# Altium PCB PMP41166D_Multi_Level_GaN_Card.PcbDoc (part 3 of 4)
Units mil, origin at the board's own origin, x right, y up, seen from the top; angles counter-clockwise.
Board outline 3221.72 x 1840 mil, 6 copper layers (Top Layer, Signal Layer 1, Signal Layer 2, Signal Layer 3, Signal Layer 4, Bottom Layer), stack 51.8 mil thick; 155 components, 123 nets, 580 pads, 278 vias.
Unrouted connection lines stored in the file: 2.
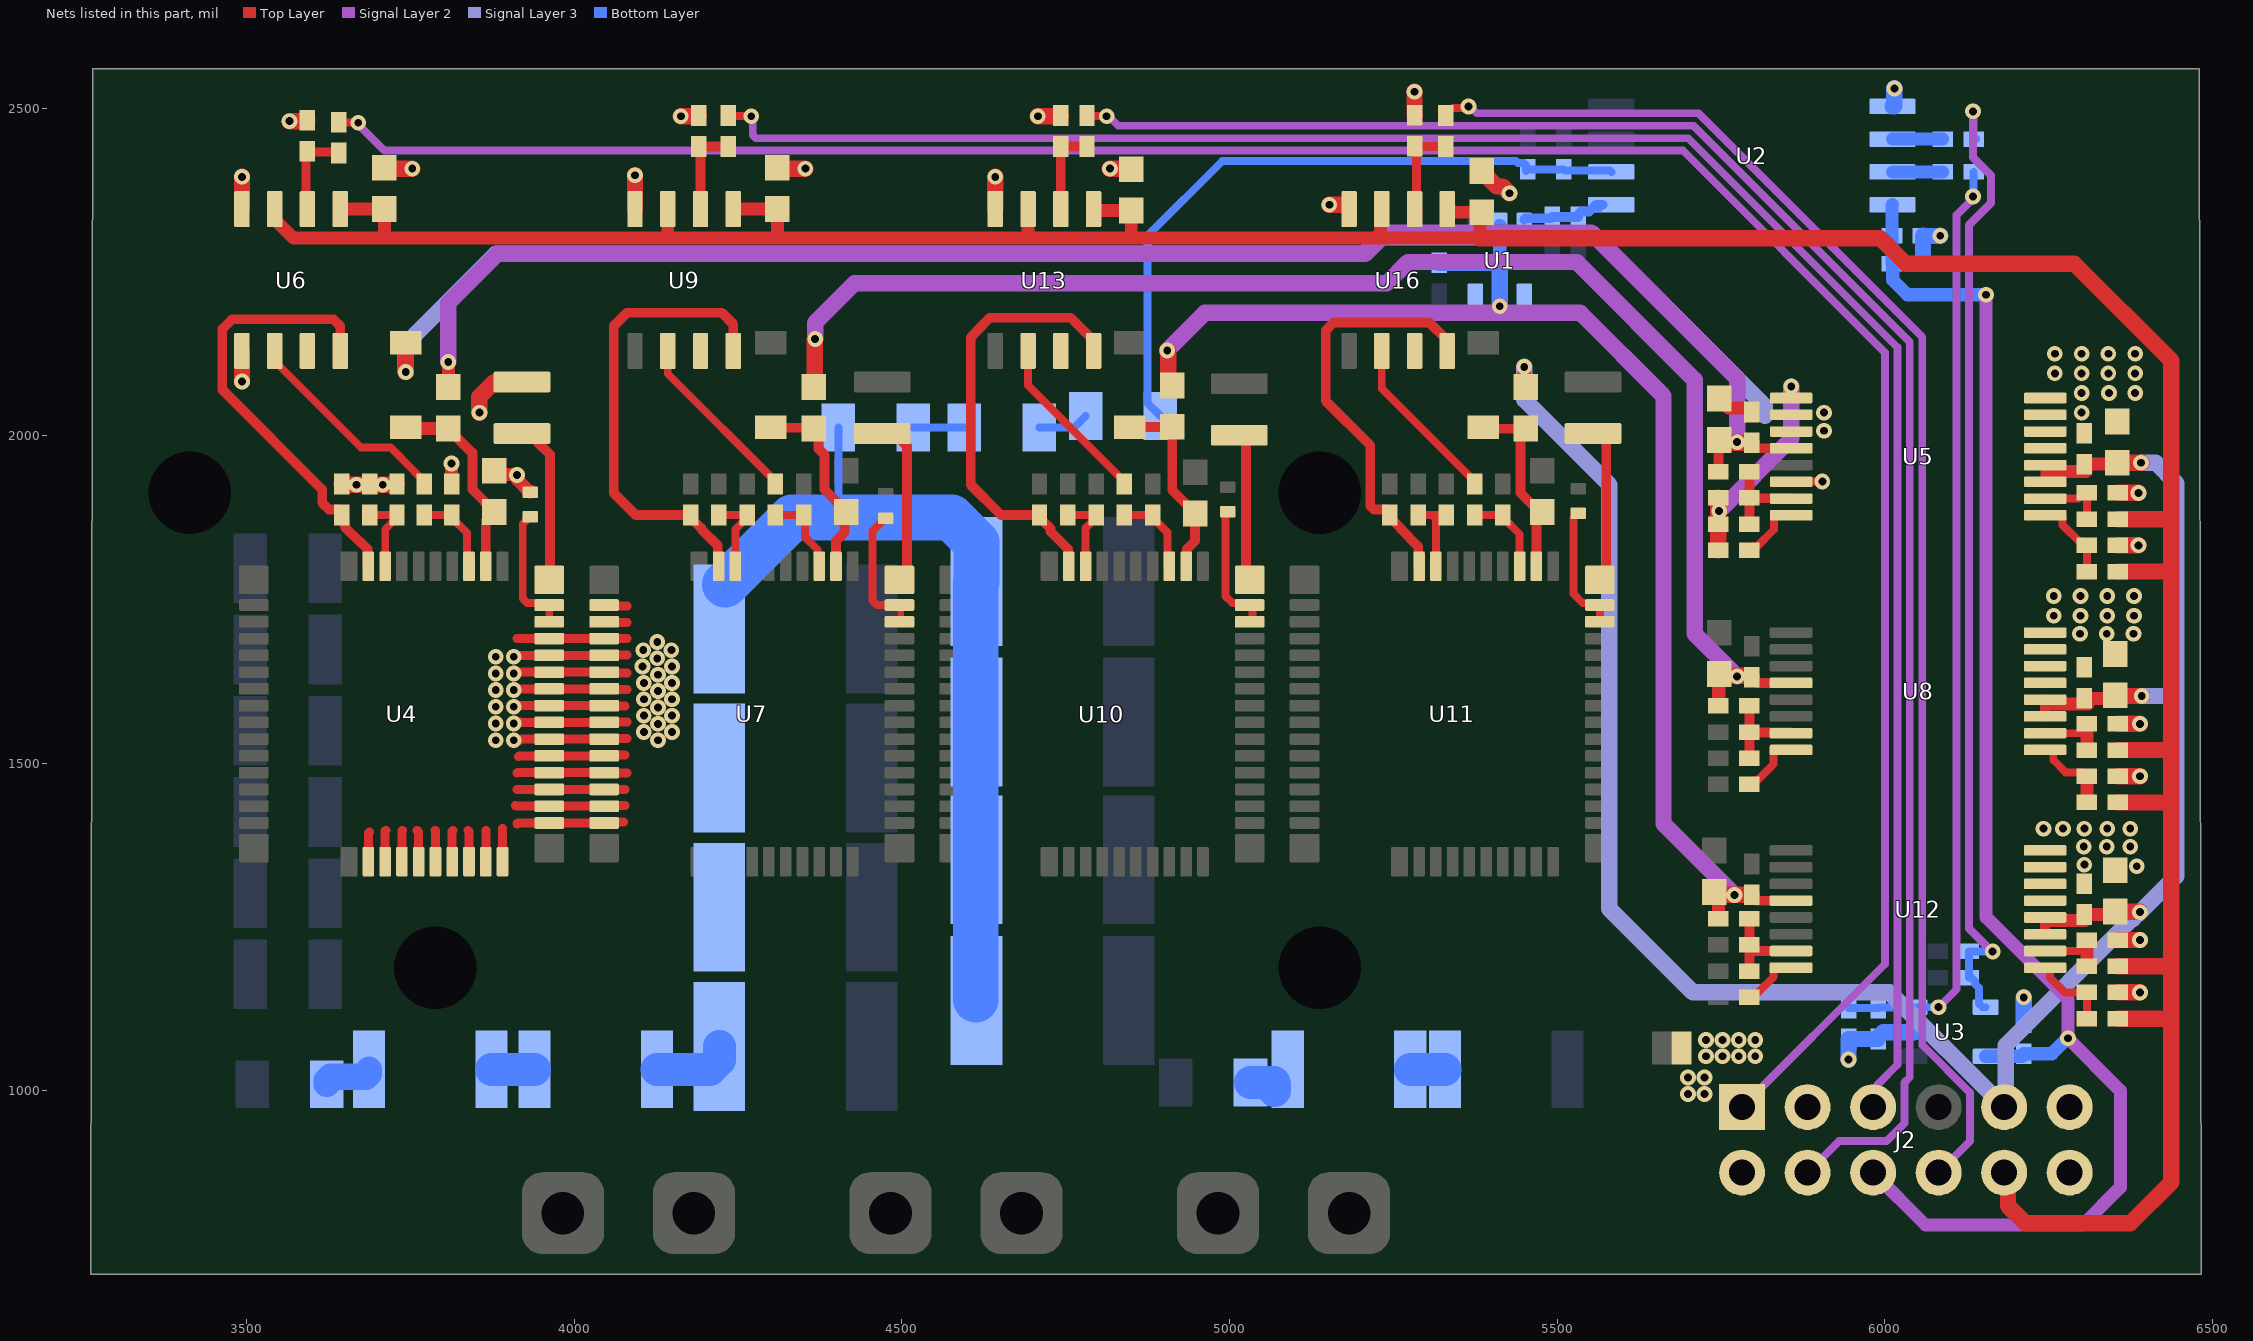
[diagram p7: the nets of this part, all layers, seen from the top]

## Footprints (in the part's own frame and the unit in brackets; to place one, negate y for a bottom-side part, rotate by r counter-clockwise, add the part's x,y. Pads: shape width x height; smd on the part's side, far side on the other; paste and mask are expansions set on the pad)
0402 [mm] "0402 from SM-752 data"
  rect 0.8x0.6 smd: 1(-0.6,0) 2(0.6,0)
  silkscreen extent -1.22,-0.52 1.22,0.52, body extent -0.55,-0.3 0.55,0.3, height 0.6
0603 [mm] "0603 from SM-752 data"
  rect 1x0.95 smd: 1(-0.8,0) 2(0.8,0)
  silkscreen extent -1.52,-0.69 1.52,0.69, body extent -0.87,-0.47 0.87,0.47, height 1
1206 [mm] "1206 from SM-752 data"
  rect 1.3x1.85 smd: 1(-1.45,0) 2(1.45,0)
  body extent -1.7,-0.9 1.7,0.9, height 1.35
1210 [mm] "1210 from SM-752 data"
  rect 1.3x2.7 smd: 1(-1.45,0) 2(1.45,0)
  silkscreen extent -2.32,-1.57 2.32,1.57, body extent -1.7,-1.35 1.7,1.35, height 1.35
AB12-DEST [mil] "Samtec right angle header, pins flipped from convention"
  rect 70x70 hole 40: 1(-250,50)
  round 70 hole 40: 2(-250,-50) 3(-150,50) 4(-150,-50) 5(-50,50) 6(-50,-50) 7(50,50) 8(50,-50) 9(150,50) 10(150,-50) 11(250,50) 12(250,-50)
  silkscreen extent -300,-479 300,100, body extent -300,-440 300,63, height 219
CKG57N [mm] "Chip Capacitor, Body 6.0x5.0x5.0mm,"
  rect 2x5 smd: 1(-2.95,0) 2(2.95,0)
  silkscreen extent -3.2,-2.8 3.2,2.8, body extent -3.3,-2.75 3.3,2.75, height 5.5
D0008B-MFG [mm]
  rrect17% 1.4x0.6 smd paste+0 mask+0: 1(-2.75,1.905) 2(-2.75,0.635) 3(-2.75,-0.635) 4(-2.75,-1.905) 5(2.75,-1.905) 6(2.75,-0.635) 7(2.75,0.635) 8(2.75,1.905)
  silkscreen extent -4.14,-2.5 1.5,2.5, body extent -3,-2.45 3,2.45, height 1.75
DBV0005A_N [mm] "SOT23, 5-Leads, Body 2.9x1.6mm, Pitch 0.95mm, Lead Span 2.8mm, IPC Medium Density"
  rrect17% 1x0.6 smd: 1(-1.375,0.95) 2(-1.375,0) 3(-1.375,-0.95) 4(1.375,-0.95) 5(1.375,0.95)
  silkscreen extent -0.25,-1.55 0.25,1.55, body extent -1.42,-1.46 1.42,1.46, height 1.09
DHA0016A-MFG [mm] "Recommended Land Pattern"
  rrect24% 1.65x0.41 smd paste+0 mask+0: 1(-4.925,2.275) 2(-4.925,1.625) 3(-4.925,0.975) 4(-4.925,0.325) 5(-4.925,-0.325) 6(-4.925,-0.975) 7(-4.925,-1.625) 8(-4.925,-2.275) 9(4.925,-2.275) 10(4.925,-1.625) 11(4.925,-0.975) 12(4.925,-0.325) 13(4.925,0.325) 14(4.925,0.975) 15(4.925,1.625) 16(4.925,2.275)
  silkscreen extent -6.43,-2.98 3.5,2.98, body extent -5.15,-2.93 5.15,2.93, height 2.6
DO-213AB [mm] "VISHAY"
  rect 1.25x3 smd: 1(-2.375,0) 2(2.375,0)
  silkscreen extent -2.79,-2.92 1.4,1.4, body extent -2.6,-1.34 2.6,1.33, height 2.66
DWV0008A-MFG [mm] "Recommended Land Pattern"
  rrect17% 1.8x0.6 smd paste+0 mask+0: 1(-5.45,1.905) 2(-5.45,0.635) 3(-5.45,-0.635) 4(-5.45,-1.905) 5(5.45,-1.905) 6(5.45,-0.635) 7(5.45,0.635) 8(5.45,1.905)
  silkscreen extent -7.1,-2.98 3.8,2.98, body extent -5.75,-2.93 5.75,2.93, height 2.8
FCC_disclaimer [mil]
"FP-GRM155R61E225KE11D_0402 (1005 metric)-MFG" [mm]
  rrect22% 0.45x0.6 smd paste+0 mask+0: 1(-0.475,0) 2(0.475,0)
  silkscreen extent -0.6,-0.64 0.6,0.65, body extent -0.5,-0.25 0.5,0.25, height 0.7
FP-MPIA2510V2-4R7-R_1008-MFG [mm]
  rrect13% 0.8x2.2 smd paste+0 mask+0: 1(-1,0) 2(1,0)
  silkscreen extent -0.23,-1.1 0.23,1.1, body extent -1.25,-1 1.25,1, height 1.05
IEC_HighVoltage_Small [mil]
  silkscreen extent -107,-88 107,97
IEC_HotSurface_Small [mil]
  silkscreen extent -107,-93 107,92
Mill-Max_3621-0-32-xx-00-00-08-0 [mm] "PCB Pin, 0.04\" DIA, R/A, Edge-Mount"
  rrect50% 3.18x3.18 hole 1.65: 1(0,2.388)
  body extent -1.59,-5.06 1.59,3.98, height 1.57
Net-Tie_50milWide_30milLong [mil] "50mil net tie, no solder mask opening, no solder paste"
  rect 30x50 smd paste-20 mask-20: 1(-15,0) 2(15,0)
RQS0052C-C01-MFG [mm]
  rrect9% 1.15x1.1 smd paste+0 mask+0: 1(-5.725,5.2) 16(-5.725,-5.2) 27(5.725,-5.2) 42(5.725,5.2)
  rrect22% 1.15x0.45 smd paste+0 mask+0: 2(-5.725,4.225) 3(-5.725,3.575) 4(-5.725,2.925) 5(-5.725,2.275) 6(-5.725,1.625) 7(-5.725,0.975) 8(-5.725,0.325) 9(-5.725,-0.325) 10(-5.725,-0.975) 11(-5.725,-1.625) 12(-5.725,-2.275) 13(-5.725,-2.925) 14(-5.725,-3.575) 15(-5.725,-4.225) 28(5.725,-4.225) 29(5.725,-3.575) 30(5.725,-2.925) 31(5.725,-2.275) 32(5.725,-1.625) 33(5.725,-0.975) 34(5.725,-0.325) 35(5.725,0.325) 36(5.725,0.975) 37(5.725,1.625) 38(5.725,2.275) 39(5.725,2.925) 40(5.725,3.575) 41(5.725,4.225)
  rrect15% 0.665x1.15 smd paste+0 mask+0: 17(-2.043,-5.725) 52(-2.043,5.725)
  rrect22% 0.45x1.15 smd paste+0 mask+0: 18(-1.285,-5.725) 19(-0.635,-5.725) 20(0.015,-5.725) 21(0.665,-5.725) 22(1.315,-5.725) 23(1.965,-5.725) 24(2.615,-5.725) 25(3.265,-5.725) 26(3.915,-5.725) 43(3.915,5.725) 44(3.265,5.725) 45(2.615,5.725) 46(1.965,5.725) 47(1.315,5.725) 48(0.665,5.725) 49(0.015,5.725) 50(-0.635,5.725) 51(-1.285,5.725)
  silkscreen extent -7.02,-6.05 4.77,6.05, body extent -6,-6 6,6, height 1
SOD-123 [mm] "On Semi recommended land pattern"
  rect 0.915x1.22 smd: 1(-1.637,0) 2(1.637,0)
  silkscreen extent -2.74,-1.17 2.03,1.17, body extent -1.93,-0.9 1.93,0.9, height 1.35
TP_H045P075 [mm] "TP_H0.45P0.75"
  round 0.75 hole 3.2: 1(0,0)
WEEE_Minimum [mil] "WEEElie bin"
  silkscreen extent -95,-172 99,104

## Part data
BULK PGND SW TP1 TP2 TP3: library part CMP-0082316-1, Manufacturer=Mill-Max, Supplier Part Number 1=575-3621032150000
C1 C25 C69: library part CMP-0081457-1, "CAP, CERM, 1 µF, 10 V,+/- 20%, X5R, 0402", Cap_Case=0402, Manufacturer="Yageo America", TempCo=X5R, Tolerance_%=20%, Value2=10V, ValueDisplayed=1µF
C2 C4 C23 C28 C51 C52 C65 C67 C70 C72 C74: library part CMP-0080610-1, "CAP, CERM, 0.1 µF, 25 V,+/- 10%, X7R, AEC-Q200 Grade 1, 0402", Cap_Case=0402, Manufacturer=TDK, Supplier Part Number 1=445-6902-1-ND, TempCo=X7R, Tolerance_%=10%, Value2=25V, ValueDisplayed=0.1µF
C3 C22 C64 C66 C71 C73: library part CMP-0007007-5, "CAP, CERM, 10 uF, 25 V, +/- 20%, X5R, 0603", Cap_Case=0603, Manufacturer=TDK, Supplier Part Number 1=445-9015-1-ND, TempCo=X5R, Tolerance_%=20%, Value1="0.004639 ohm", Value2=25V, ValueDisplayed=10uF
C5 C6 C7 C8 C9 C10: library part CMP-0009136-2, "CAP, CERM, 0.1 uF, 630 V, +/- 10%, X7T, 1210", Cap_Case=1210, Manufacturer=TDK, Supplier Part Number 1=445-7766-1-ND, TempCo=X7T, Tolerance_%=10%, Value1=Unknown, Value2=630V, ValueDisplayed=0.1uF
C11 C30 C44 C58: library part CMP-0007344-5, "CAP, CERM, 10 uF, 25 V, +/- 20%, X5R, 0603", Cap_Case=0603, Manufacturer=MuRata, Supplier Part Number 1=490-7202-1-ND, TempCo=X5R, Tolerance_%=20%, Value1=Unknown, Value2=25V, ValueDisplayed=10uF
C12 C13 C14 C15 C16 C17 C18 C19: library part CMP-0009428-1, "CAP, CERM, 2.2 uF, 450 V, +/- 20%, X7T, AEC-Q200 Grade 1, 6x5x5mm", Cap_Case=2220, Manufacturer=TDK, Supplier Part Number 1=445-7109-1-ND, TempCo=X7T, Tolerance_%=20%, Value1=Unknown, Value2=450V, ValueDisplayed=2.2uF
C20 C57 C80 C96: library part CMP-0007359-4, "CAP, CERM, 0.1 uF, 6.3 V, +/- 10%, X7R, 0603", Cap_Case=0603, Manufacturer=MuRata, Supplier Part Number 1=GRM188R70J104KA01D-ND, TempCo=X7R, Tolerance_%=10%, Value1=Unknown, Value2=6.3V, ValueDisplayed=0.1uF
C21 C40 C45 C59: library part CMP-0078265-1, "CAP, CERM, 0.22 µF, 16 V,+/- 10%, X7R, AEC-Q200 Grade 1, 0402", Cap_Case=0402, Manufacturer=MuRata, Supplier Part Number 1=490-10671-1-ND, TempCo=X7R, Tolerance_%=10%, Value2=16V, ValueDisplayed=0.22µF
C24 C68 C75: library part CMP-0006691-2, "CAP, CERM, 470 pF, 50 V, +/- 10%, X7R, 0402", Cap_Case=0402, Manufacturer=MuRata, Supplier Part Number 1=490-1300-1-ND, TempCo=X7R, Tolerance_%=10%, Value1=Unknown, Value2=50V, ValueDisplayed=470pF
C26 C63 C86 C98: library part CMP-0006251-2, "CAP, CERM, 68 pF, 50 V, +/- 5%, C0G/NP0, 0402", Alternate Manufacturer=Murata, Alternate PartNumber=GRM1555C1H680JA01D, Cap_Case=0402, Manufacturer=TDK, Supplier Part Number 1=445-1245-1-ND, TempCo=C0G/NP0, Tolerance_%=5%, Value1=Unknown, Value2=50V, ValueDisplayed=68pF
C27 C42 C47 C61: library part CMP-0006308-1, "CAP, CERM, 100 pF, 50 V, +/- 5%, C0G/NP0, AEC-Q200 Grade 1, 0402", Cap_Case=0402, Manufacturer=TDK, Supplier Part Number 1=445-5596-1-ND, TempCo=C0G/NP0, Tolerance_%=5%, Value1=Unknown, Value2=50V, ValueDisplayed=100pF
C29 C43 C48 C62: library part CMP-0089929-1, "2.2µF ±10% 25V Ceramic Capacitor X5R 0402 (1005 Metric)", Digikey Part Number=490-12703-1-ND, Manufacturer=Murata, Mouser Part Number=81-GRM155R61E225KE1D, Operating Temperature Range="-55°C to +85°C", TempCo=15%, Temperature Characteristic=X5R, Tolerance_%=10%, ValueDisplayed=2.2uF, Voltage=25V
C31 C41 C46 C60: library part CMP-0006439-2, "CAP, CERM, 22 pF, 50 V, +/- 5%, C0G/NP0, 0402", Cap_Case=0402, Manufacturer=MuRata, Supplier Part Number 1=81-GRM1555C1H220JA1D, TempCo=C0G/NP0, Tolerance_%=5%, Value1=Unknown, Value2=50V, ValueDisplayed=22pF
C49: library part CMP-0006297-2, "CAP, CERM, 0.1 uF, 50 V, +/- 10%, X7R, 0402", Cap_Case=0402, Manufacturer=TDK, Supplier Part Number 1=445-5932-1-ND, TempCo=X7R, Tolerance_%=10%, Value1="0.039064 ohm", Value2=50V, ValueDisplayed=0.1uF
C50 C100: library part CMP-0006455-2, "CAP, CERM, 330 pF, 50 V, +/- 1%, C0G/NP0, 0402", Cap_Case=0402, Manufacturer=MuRata, Supplier Part Number 1=490-6234-1-ND, TempCo=C0G/NP0, Tolerance_%=1%, Value1=Unknown, Value2=50V, ValueDisplayed=330pF
C53 C54 C55: library part CMP-0078625-1, "CAP, CERM, 1 µF, 25 V,+/- 20%, X5R, 0402", Cap_Case=0402, Manufacturer=MuRata, Supplier Part Number 1=490-10018-1-ND, TempCo=X5R, Tolerance_%=20%, Value2=25V, ValueDisplayed=1µF
C56: library part CMP-0006663-2, "CAP, CERM, 2200 pF, 25 V, +/- 10%, X7R, 0402", Cap_Case=0402, Manufacturer=MuRata, Supplier Part Number 1=490-5419-1-ND, TempCo=X7R, Tolerance_%=10%, Value1=Unknown, Value2=25V, ValueDisplayed=2200pF
D2 D3 D5 D6: library part CMP-0082173-3, "Diode, Zener, 150V", Manufacturer=Vishay-Semiconductor, PartNumber=ZGL41-150A-E3/96, Power_W=1W
D8 D9 D10 D11: library part CMP-0005769-2, "Diode, Zener, 16 V, 500 mW, AEC-Q101, SOD-123", Manufacturer="Diodes Inc.", Power_W=500mW, Supplier Part Number 1=BZT52C16-FDICT-ND, Value1=0.5W
J2: library part CMP-0075414-2, "Header, 100mil, 6x2, Gold, R/A, TH", Color=Black, Current_A=6.3A, Manufacturer=Samtec, Supplier Part Number 1=SAM1037-06-ND, Voltage_V=550V
L4 L5 L6 L7: library part CMP-0090507-1, "4.7µH Shielded Molded Inductor 1.22A 262mOhm Max 1008 (2520 Metric)", Digikey Part Number=283-4799-1-ND, Manufacturer=Eaton, Mouser Part Number=704-MPIA2510V2-4R7-R, Operating Temperature Range="-40°C to +125°C", Self Resonant Frequency=25MHz, Test Frequency=1MHz, Tolerance_%=20%
Logo1: library part CMP-0074769-1
Logo3: library part CMP-0074847-1, "FCC_disclaimer"
LOGO5: library part CMP-0074837-1, "IEC 61010-1 Hot Surface Warning"
LOGO6: library part CMP-0074835-1, "IEC 61010-1 High Voltage Warning"
NT1: library part CMP-0078142-4, "Single point connection between nets.", Manufacturer=N/A
R1 R2 R3 R4: library part CMP-0026918-5, "RES, 3.3 k, 5%, 0.063 W, AEC-Q200 Grade 0, 0402", Manufacturer=Vishay-Dale, Power_W=63mW, Supplier Part Number 1=541-3.3KJCT-ND, TempCo="200 ppm/C", Tolerance_%=5%, Value2=0.063W, Value_Code=3k30, ValueDisplayed=3.3k
R5 R8 R11 R25: library part CMP-0025883-3, "RES, 0, 5%, 0.1 W, 0603", Manufacturer=Rohm, Power_W=100mW, Supplier Part Number 1=RHM0.0GCT-ND, TempCo="400 ppm/C", Tolerance_%=5%, Value2=0.1W, Value_Code=0000, ValueDisplayed=0
R6 R9 R12 R27: library part CMP-0026902-3, "RES, 300, 5%, 0.063 W, AEC-Q200 Grade 0, 0402", Manufacturer=Vishay-Dale, Power_W=63mW, Supplier Part Number 1=541-300JCT-ND, TempCo="200 ppm/C", Tolerance_%=5%, Value2=0.063W, Value_Code=300R, ValueDisplayed=300
R7 R10 R13 R14: library part CMP-0026720-1, "RES, 69.8 k, 1%, 0.063 W, 0402", Manufacturer=Rohm, Power_W=63mW, TempCo="100 ppm/C", Tolerance_%=1%, Value2=0.063W, Value_Code=69k8, ValueDisplayed=69.8k
R15 R19 R20 R24 R26 R33: library part CMP-0065360-1, "RES, 10.0 k, .1%, .0625 W, 0402", Manufacturer="Yageo America", Power_W=62.5mW, Supplier Part Number 1=YAG1346CT-ND, TempCo="25 ppm/C", Tolerance_%=0.1%, Value1=.1%, Value2=.0625W, Value_Code=10k0, ValueDisplayed=10.0k
R16 R21 R29: library part CMP-0026463-2, "RES, 5.11 k, 1%, 0.063 W, AEC-Q200 Grade 0, 0402", Manufacturer=Vishay-Dale, Power_W=63mW, Supplier Part Number 1=541-5.11KLCT-ND, TempCo="100 ppm/C", Tolerance_%=1%, Value2=0.063W, Value_Code=5k11, ValueDisplayed=5.11k
R17 R22 R31: library part CMP-0026723-1, "RES, 180 k, 1%, 0.063 W, 0402", Manufacturer="Yageo America", Power_W=63mW, Supplier Part Number 1=311-180KLRCT-ND, TempCo="100 ppm/C", Tolerance_%=1%, Value2=0.063W, Value_Code=180k
R18 R23 R32: library part CMP-0026323-1, "RES, 38.3 k, 1%, 0.063 W, 0402", Manufacturer=Vishay-Dale, Power_W=63mW, Supplier Part Number 1=541-38.3KLCT-ND, TempCo="100 ppm/C", Tolerance_%=1%, Value2=0.063W, Value_Code=38k3, ValueDisplayed=38.3k
R28 R40 R60 R74: library part CMP-0026404-2, "RES, 49.9, 1%, 0.063 W, AEC-Q200 Grade 0, 0402", Manufacturer=Vishay-Dale, Power_W=63mW, Supplier Part Number 1=541-49.9LCT-ND, TempCo="100 ppm/C", Tolerance_%=1%, Value2=0.063W, Value_Code=49R9, ValueDisplayed=49.9
R30 R63: library part CMP-0018790-2, "RES, 10.0, 0.1%, 1 W, 1206", Manufacturer=Vishay-Dale, Power_W=1W, Supplier Part Number 1=PHP10.0ACT-ND, TempCo="25 ppm/C", Tolerance_%=0.1%, Value_Code=10R0, ValueDisplayed=10.0
R42 R46 R48: library part CMP-0018215-2, "RES, 348 k, 1%, 0.25 W, 1206", Manufacturer="Yageo America", Power_W=250mW, Supplier Part Number 1=311-348KFRCT-ND, TempCo="100 ppm/C", Tolerance_%=1%, Value2=0.25W, Value_Code=348k
R53: library part CMP-0026555-2, "RES, 7.50 k, 1%, 0.063 W, AEC-Q200 Grade 0, 0402", Manufacturer=Vishay-Dale, Power_W=63mW, Supplier Part Number 1=541-7.50KLCT-ND, TempCo="100 ppm/C", Tolerance_%=1%, Value2=0.063W, Value_Code=7k50, ValueDisplayed=7.50k
TH1 TH2 TH3 TH4: library part CMP-0003719-1, "Testpoint", Manufacturer="Texas Instruments", PartNumber=TP_H0.45P0.75
U1: library part CMP-0035558-1, "Single Output LDO, 150 mA, Fixed 5 V Output, 2.5 to 24 V Input, with Ultra-Low IQ, 5-pin SOT-23 (DBV), -40 to 125 degC, Green (RoHS & no Sb/Br)", Manufacturer="Texas Instruments"
U2: library part CMP-0124041-1, "Precision, 2V Input, Basic and Reinforced Isolated Amplifiers With Fixed-Gain Differential Output", Input Bias Current=3.5nA, Input Offset Voltage=0.2mV, Manufacturer="Texas Instruments", Max Supply Voltage=5.5V, Min Supply Voltage=3V, Operating Temperature Range="-40°C to +125°C", Output Current Per Channel=11mA, Voltage Gain=1V/V
U3: library part CMP-0750075-1, "10-MHz, RRIO, CMOS Operational Amplifier for Cost-Sensitive Systems, DBV0005A (SOT-23-5)", Alternate Manufacturer="Texas Instruments"
U4 U7 U10 U11: library part CMP-0094892-1, "650-V 30-mΩ GaN FET with Integrated Driver, Protection, and Temperature Reporting", Manufacturer="Texas Instruments", Max Supply Voltage=18V, Min Supply Voltage=7.5V, Nominal Supply Current=16mA, Operating Temperature Range="-40°C to +150°C", Output Voltage=520V, Part Number=LMG3525R030-Q1
U5 U8 U12: library part CMP-0126653-2, "Automotive 2.0W, 12V VIN, High-Density, > 5kVRMS, Isolated DC/DC Module", Manufacturer="Texas Instruments", Max Supply Voltage=20V, Min Supply Voltage=5.5V, Operating Temperature Range="-40°C to +150°C", Output Voltage=-2-8/12-18V
U6 U9 U13 U16: library part CMP-0089765-2, "General Purpose Digital Isolator 3000Vrms 1 Channel 100Mbps 85kV/µs CMTI 8-SOIC (0.154\", 3.90mm Width)", Digikey Part Number=296-51194-1-ND, Manufacturer="Texas Instruments", Max Supply Voltage=5.5V, Min Supply Voltage=2.25V, Mouser Part Number=595-ISO7710FDR, Nominal Supply Current=156-311mA, Operating Temperature Range="-55°C to +125°C"

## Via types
v1: diameter 24, hole 12, Top Layer to Bottom Layer, tented both sides, 278 vias

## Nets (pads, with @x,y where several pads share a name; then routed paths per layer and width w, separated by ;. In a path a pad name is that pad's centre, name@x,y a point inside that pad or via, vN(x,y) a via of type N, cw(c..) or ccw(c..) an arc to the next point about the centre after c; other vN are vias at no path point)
3V3: C52.2 C53.2 C55.2 J2.6 U2.8 U3.5 | length 2287.8
  Signal Layer 2 w20: J2.6@5982.5,875 6062.5,795 6302.5,795 6360,852.5 6360,1000 v1(6280,1080) 6280,1139.5 6155,1264.5 v1(6155,2215)
  Bottom Layer w20: U2.8@6012.07,2352.5 6011.38,2351.81 C52.2@6011.38,2305 C55.2@6011.38,2262.5 6012.5,2261.38 6012.5,2237.5 6035,2215 v1(6155,2215) ; U3.5@6154.13,1052.6 6210.69,1052.6 6212.5,1054.41 C53.2@6212.5,1056.38 6255.3,1056.38 6278.92,1080 v1(6280,1080)
5Vp: C20.1 C57.1 C80.1 C96.1 J2.10 R15.2 R16.2 R20.2 R21.2 R26.2 R29.2 U6.1 U6.3 U9.1 U9.3 U13.1 U13.3 U16.1 U16.3 | length 5636.9
  Top Layer w13.78: U6.3@3542.5,2330.02 U6.3@3542.5,2345.77 ; U9.3@4142.5,2335 U9.3@4142.5,2345.77 ; U13.3@4692.5,2323.57 U13.3@4692.5,2345.77
  Top Layer w19.68: U6.3@3542.5,2330.02 3571.15,2301.37 3710,2301.37 ; U6.1@3642.5,2345.77 3642.62,2345.89 3709.88,2345.89 C20.1@3710,2346 3710,2301.37 ; U9.3@4142.5,2335 4142.5,2301.37 ; U9.1@4242.5,2345.77 4242.62,2345.89 4309.88,2345.89 C57.1@4310,2346 4310,2303.87 4307.5,2301.37 ; U13.3@4692.5,2323.57 4692.5,2301.37 ; U13.1@4792.5,2345.77 4792.5,2345.47 4794.47,2343.5 C80.1@4850,2343.5 4850,2303.87 4847.5,2301.37 ; U16.3@5232.5,2345.77 5230.53,2343.8 5230.53,2301.9 5230,2301.37 ; U16.1@5337.5,2345.77 5342.26,2341 C96.1@5385,2341 5382.5,2338.5 5382.5,2301.37 5230,2301.37 ; 3710,2301.37 4142.5,2301.37 ; 4142.5,2301.37 4307.5,2301.37 ; 4307.5,2301.37 4692.5,2301.37 ; 4692.5,2301.37 4847.5,2301.37 ; 4847.5,2301.37 5230,2301.37
  Top Layer w25: 5382.5,2301.37 5993.63,2301.37 6032.5,2262.5 6289.55,2262.5 6437.5,2114.55 6437.5,1875 ; J2.10@6182.5,875 6188.42,869.08 6188.42,824.08 6215,797.5 6375,797.5 6437.5,860 6437.5,1112.5 ; R29.2@6356.12,1110 6435,1110 6437.5,1112.5 ; R26.2@6356.12,1190 6437.5,1190 ; R21.2@6356.12,1440 6435,1440 6437.5,1442.5 ; R20.2@6356.12,1520 6437.5,1520 ; R16.2@6356.12,1792.5 6437.5,1792.5 ; R15.2@6356.12,1872.5 6435,1872.5 6437.5,1875 ; 6437.5,1112.5 6437.5,1190 ; 6437.5,1190 6437.5,1442.5 ; 6437.5,1442.5 6437.5,1520 ; 6437.5,1520 6437.5,1792.5 ; 6437.5,1792.5 6437.5,1875
12Vp: C3.1 C4.1 C64.1 C65.1 C71.1 C72.1 J2.9 R11.1 U5.3 U5.4 U8.3 U8.4 U12.3 U12.4 | length 3343.2
  Top Layer w12: U12.4@6245,1264.41 U12.4@6245.59,1265 ; U8.4@6245,1596.91 U8.4@6245.98,1597.89 ; U5.4@6245.3,1955 U5.4@6245.98,1955.69 ; C72.1@6301.12,1265 C72.1@6305,1268.88 ; C65.1@6304.02,1597.89 C65.1@6305,1598.88 ; C4.1@6304.31,1955.69 C4.1@6305,1956.38 ; C71.1@6347.87,1268.88 C71.1@6352.5,1273.5 ; C64.1@6347.87,1598.88 C64.1@6352.5,1603.5 ; C3.1@6352.87,1956.38 C3.1@6355,1958.5
  Top Layer w15: U12.3@6245,1238.82 U12.4@6245,1264.41 ; U8.3@6245,1571.32 U8.4@6245,1596.91 ; U5.3@6245.3,1929.41 U5.4@6245.3,1955 ; C71.1@6352.5,1273.5 C71.1@6353,1273 ; v1@6389.5,1273 v1(6390,1272.5)
  Top Layer w20: R11.1@5450,2074 v1(5450,2105) ; U12.4@6250,1260 C72.1@6305.53,1260 ; 6251.67,1945 C4.1@6307.5,1945 ; U8.4@6252.5,1590 C65.1@6310.53,1590 ; C72.1@6305,1268.88 C71.1@6347.87,1268.88 ; C65.1@6305,1598.88 C64.1@6347.87,1598.88 ; C4.1@6305,1956.38 C3.1@6352.87,1956.38
  Top Layer w25: C64.1@6352.5,1603.5 6353.5,1602.5 v1(6392.5,1602.5) ; C71.1@6353,1273 v1@6389.5,1273 ; C3.1@6355,1958.5 v1(6391.62,1958.5)
  Signal Layer 3 w25: v1(5450,2105) 5450,2055 5580,1925 5580,1277.5 5707.5,1150 6007.5,1150 J2.9@6182.5,975 6185,977.5 6185,1069.55 6376.95,1261.5 6379,1261.5 v1(6390,1272.5) 6445,1327.5 6445,1602.5 ; v1(6391.62,1958.5) 6414,1958.5 6445,1927.5 6445,1602.5 ; v1(6392.5,1602.5) 6445,1602.5
CFLYSENSE: C56.1 R48.1 R53.2 U2.2 | length 1048.9
  Bottom Layer w12: R48.1@4894.59,2030 4875,2049.59 4875,2305 4989,2419 5437.38,2419 5440.25,2416.13 5449.19,2416.13 5452.5,2412.82 R53.2@5452.5,2403.88 ; R53.2@5455,2406.38 C56.1@5510,2406.38 5511.94,2404.44 5580.99,2404.44 U2.2@5582.93,2402.5
HFFET_H2A: J2.1 R28.1 | length 3749.9
  Top Layer w12: R28.1@3640,2478.62 3640.56,2478.06 3669.44,2478.06 v1(3670,2477.5)
  Signal Layer 2 w12: v1(3670,2477.5) 3670,2475 3710,2435 5692.5,2435 6000.5,2127 6000.5,1193 J2.1@5782.5,975
HFFET_H3A: J2.5 R40.1 | length 3121.7
  Top Layer w12: R40.1@4235,2488.62 4235.56,2488.06 4269.44,2488.06 v1(4270,2487.5)
  Signal Layer 2 w12: v1(4270,2487.5) 4272.3,2485.2 4272.3,2458.73 4277.03,2454 5700.37,2454 6019.5,2134.87 6019.5,1039.5 5990,1010 5990,982.5 J2.5@5982.5,975
HFFET_L2B: J2.8 R74.1 | length 2207
  Top Layer w12: R74.1@5330,2488.62 5330,2492.56 5335.81,2498.37 5339.75,2498.37 5341.58,2500.2 5362.7,2500.2 v1(5365,2502.5)
  Signal Layer 2 w12: v1(5365,2502.5) 5367,2502.5 5377.5,2492 5716.11,2492 6057.5,2150.61 6057.5,1070 6130.5,997 6130.5,923 J2.8@6082.5,875
HFFET_L3B: J2.4 R60.1 | length 2773.9
  Top Layer w12: R60.1@4782.5,2488.62 4783.06,2488.06 4811.94,2488.06 v1(4812.5,2487.5)
  Signal Layer 2 w12: v1(4812.5,2487.5) 4815.75,2487.5 4830.25,2473 5708.24,2473 5823,2358.24 ; 5823.12,2358.12 6038.5,2142.74 6038.5,1020.5 6030.5,1012.5 6030.5,950.5 6003,923 5930.5,923 J2.4@5882.5,875
ISO_12V_H2A: C22.1 C23.1 R18.1 R25.1 U5.12 | length 2495.2
  Top Layer w12: C22.1@5746.38,1988.88 5746.38,1992.38 C22.1@5747.5,1993.5 ; C23.1@5797.5,1988.88 5797.5,1986.4 C23.1@5803.31,1980.59
  Top Layer w15: R18.1@5746.38,1945 C22.1@5746.38,1988.88 ; C23.1@5803.31,1980.59 U5.12@5857.5,1980.59
  Top Layer w19.68: R25.1@3807.5,2074 v1(3807.5,2112.5)
  Top Layer w25: C22.1@5746.38,1988.88 C23.1@5797.5,1988.88
  Signal Layer 2 w25: v1(3807.5,2112.5) 3807.5,2202.5 3882.5,2277.5 5207.5,2277.5 5240,2310 5552.5,2310 5775,2087.5 v1(5775,1990)
ISO_12V_H3A: C66.1 C67.1 R5.1 R23.1 U8.12 | length 2200.6
  Top Layer w12: C67.1@5797.5,1631.38 5797.5,1628.31 C67.1@5803.31,1622.5
  Top Layer w15: C67.1@5803.31,1622.5 U8.12@5857.2,1622.5
  Top Layer w19.68: R5.1@4365,2074 R5.1@4366.67,2075.67 ; v1@4366.67,2146.67 v1(4367.5,2147.5)
  Top Layer w20: R23.1@5746.94,1588.06 C66.1@5746.94,1635.44
  Top Layer w25: R5.1@4366.67,2075.67 v1@4366.67,2146.67 ; C66.1@5746.94,1635.44 C66.1@5747.5,1636 5749.81,1633.69 5796.81,1633.69 5797.5,1633 C67.1@5797.5,1631.38
  Signal Layer 2 w25: v1(4367.5,2147.5) 4367.5,2172.5 4427.5,2232.5 5240,2232.5 5272.5,2265 5530,2265 5710,2085 5710,1697.5 v1(5775,1632.5)
ISO_12V_L3B: C49.1 C73.1 C74.1 R8.1 R32.1 U1.2 U12.12 | length 2079.8
  Top Layer w12: C73.1@5740,1303.5 5744.63,1298.88 C73.1@5746.38,1297.13 ; C74.1@5797.5,1298.88 5797.5,1295.81 C74.1@5803.31,1290
  Top Layer w15: C74.1@5803.31,1290 U12.12@5857.2,1290
  Top Layer w20: R32.1@5746.38,1262.5 C73.1@5746.38,1297.13
  Top Layer w25: v1(4905,2130) 4906.3,2128.7 4906.3,2082.7 R8.1@4912.5,2076.5 ; C73.1@5744.63,1298.88 v1(5771.06,1298.88) C74.1@5797.5,1298.88
  Signal Layer 2 w25: v1(4905,2130) 4962.5,2187.5 5535.5,2187.5 5662.5,2060.5 5662.5,1407.5 v1(5771.06,1298.88) v1(5771.06,1298.88) ; v1@5412.5,2190 v1(5412.5,2197.5)
  Bottom Layer w20: 5412.51,2263.62 U1.2@5412.6,2320.77
  Bottom Layer w25: C49.1@5320,2263.62 5411.38,2263.62 ; v1(5412.5,2197.5) 5412.5,2262.5
NCU1: U1.4
NCU1': U1.5
NCU6: U6.7
NCU9: U9.7
NCU13: U13.7
NCU16: U16.7
NetC1_1: C1.1 R15.1 U5.2 | length 107.2
  Top Layer w12: U5.2@6245.3,1903.82 6296.26,1903.82 6304.94,1912.5 C1.1@6308.88,1912.5 R15.1@6308.88,1872.5
NetC2_1: C2.1 R16.1 U5.1 | length 129.8
  Top Layer w12: U5.1@6245.3,1878.23 6269.7,1878.23 6271.78,1876.16 6271.78,1863.66 6297.12,1838.31 6303.07,1838.31 C2.1@6308.88,1832.5 R16.1@6308.88,1792.5
NetC11_1: C11.1 D8.1 R25.2 U4.44 | length 310.3
  Top Layer w10: C11.1@3864.69,1870.69 C11.1@3877.5,1883.5
  Top Layer w12: R25.2@3807.26,2010.77 R25.2@3815.8,2002.23
  Top Layer w15: R25.2@3815.8,2002.23 3815.8,2001.72 3843.22,1974.3 3844.3,1974.3 3844.3,1917.69 3877.5,1884.49 C11.1@3877.5,1883.5 ; U4.44@3864.69,1800.39 C11.1@3864.69,1870.69
  Top Layer w20: D8.1@3742.5,2010.53 3742.74,2010.77 R25.2@3807.26,2010.77
NetC21_1: C21.1 U4.51 U6.8 | length 693.6
  Top Layer w15: U6.8@3643.11,2128.62 U6.8@3642.5,2129.23 3642.5,2167.5 3632.5,2177.5 3477.5,2177.5 3462.5,2162.5 3462.5,2070 3615,1917.5 3615,1897.5 3625.37,1887.13 3640.69,1887.13 3645,1882.82 C21.1@3645,1878.88 3649.31,1874.57 3649.31,1860.69 3672.47,1837.53 3673.65,1837.53 3684.19,1826.99 3684.19,1801.75 U4.51@3685.55,1800.39
NetC24_1: C24.1 R18.2 R19.2 U5.15 | length 157.9
  Top Layer w10: R18.2@5782.87,1951.81 5789.69,1945 R18.2@5793.62,1945
  Top Layer w12: R19.2@5793.62,1905 R19.2@5794.21,1904.41 ; U5.15@5856.91,1904.41 U5.15@5857.5,1903.82
  Top Layer w15: C24.1@5793.62,1865 R19.2@5793.62,1905 R18.2@5793.62,1945 ; R19.2@5794.21,1904.41 U5.15@5856.91,1904.41
NetC25_1: C25.1 R20.1 U8.2 | length 106.3
  Top Layer w12: U8.2@6245,1545.73 6303.15,1545.73 6308.88,1540
  Top Layer w20: R20.1@6308.88,1520 6308.88,1540 C25.1@6308.88,1560
NetC26_1: C26.1 R28.2 U6.2 | length 137.6
  Top Layer w13.78: C26.1@3590.18,2433.88 3590.18,2348.08 U6.2@3592.5,2345.77 ; C26.1@3592.5,2433.88 3593.75,2432.63 3638.75,2432.63 R28.2@3640,2431.38
NetC27_1: C27.1 R7.2 U4.50 | length 127.6
  Top Layer w12: R7.2@3687.5,1878.88 C27.1@3729.17,1878.88 3729.17,1874.94 3711.14,1856.92 U4.50@3711.14,1800.39
NetC28_1: C28.1 R21.1 U8.1 | length 128.2
  Top Layer w12: U8.1@6245,1520.14 6255.43,1520.14 6257.5,1518.07 6257.5,1505 6276.69,1485.81 6303.07,1485.81 C28.1@6308.88,1480
  Top Layer w20: R21.1@6308.88,1440 C28.1@6308.88,1480
NetC29_2: C29.2 U4.40 U4.41 | length 201.5
  Top Layer w12: C29.2@3932.5,1876.3 3929.55,1876.3 3926.69,1873.44 3926.69,1870.49 3921.2,1865 3921.2,1751.3 3928.3,1744.2 3958.68,1744.2 U4.41@3961.54,1741.34 U4.40@3961.54,1715.75
NetC30_1: C30.1 D9.1 R5.2 U7.44 | length 297.9
  Top Layer w15: D9.1@4300,2013.03 4301.01,2012.02 R5.2@4358.99,2012.02 ; R5.2@4362.5,2008.5 4362.81,2008.5 4372.5,1998.82 4372.5,1980 4381.8,1970.7 4381.8,1917.69 4415,1884.49 C30.1@4415,1883.5 4412.5,1881 4412.5,1852.5 4399.3,1839.3 U7.44@4399.3,1800.39 U7.44@4397.95,1801.75
NetC31_1: C31.1 R27.2 U4.45 | length 131.2
  Top Layer w12: R27.2@3770.83,1878.88 C31.1@3812.5,1878.88 3812.5,1874.94 3836.24,1851.2 3836.24,1803.25 U4.45@3839.09,1800.39
NetC40_1: C40.1 U7.51 U9.8 | length 721.4
  Top Layer w15: U7.51@4220.17,1800.39 4218.81,1801.75 4218.81,1832.32 4194.31,1856.82 4194.31,1858.13 4177.5,1874.94 C40.1@4177.5,1878.88 4093.62,1878.88 4060,1912.5 4060,2167.5 4080,2187.5 4225,2187.5 4242.5,2170 U9.8@4242.5,2129.23
NetC41_1: C41.1 R6.2 U7.45 | length 131.4
  Top Layer w12: R6.2@4306.88,1878.88 C41.1@4350,1878.88 4352.13,1876.75 4352.13,1845.13 4370.86,1826.4 4370.86,1803.25 U7.45@4373.71,1800.39
NetC42_1: C42.1 R10.2 U7.50 | length 129.1
  Top Layer w12: R10.2@4220.62,1878.88 4263.75,1878.88 4263.75,1874.94 4245.76,1856.95 U7.50@4245.76,1800.39
NetC43_2: C43.2 U7.40 U7.41 | length 204.8
  Top Layer w10: U7.40@4498.29,1716.04 U7.41@4498.29,1741.34
  Top Layer w12: C43.2@4475,1873.8 4472.05,1873.8 4469.19,1870.94 4469.19,1867.99 4455,1853.8 4455,1748.37 4462.03,1741.34 U7.41@4496.15,1741.34
NetC44_1: C44.1 D10.1 R8.2 U10.44 | length 298.4
  Top Layer w15: D10.1@4847.5,2013.03 4847.74,2013.27 4912.26,2013.27 R8.2@4912.5,2013.5 4912.5,1916.99 4947.5,1881.99 C44.1@4947.5,1881 4947.5,1839.24 4935.28,1827.02 4935.28,1801.75 U10.44@4933.92,1800.39
NetC45_1: C45.1 U10.51 U13.8 | length 678.4
  Top Layer w15: U10.51@4754.79,1800.39 4753.43,1801.75 4753.43,1826.99 4726.81,1853.61 4726.81,1858.13 4710,1874.94 C45.1@4710,1878.88 4651.12,1878.88 4605,1925 4605,2150 4615.43,2160.43 4615.43,2160.86 4634.57,2180 4757.5,2180 4768.11,2169.39 ; 4768.11,2169.37 4792.5,2144.98 U13.8@4792.5,2129.23 U13.8@4791.25,2127.98
NetC46_1: C46.1 R9.2 U10.45 | length 132.3
  Top Layer w12: R9.2@4839.38,1878.88 C46.1@4882.5,1878.88 4882.5,1874.94 4905.48,1851.97 4905.48,1803.25 U10.45@4908.33,1800.39
NetC47_1: C47.1 R13.2 U10.50 | length 128.2
  Top Layer w12: R13.2@4753.12,1878.88 C47.1@4796.25,1878.88 4796.25,1874.94 4780.38,1859.07 U10.50@4780.38,1800.39
NetC48_2: C48.2 U10.40 U10.41 | length 199.1
  Top Layer w12: C48.2@4997.5,1883.8 4996.56,1883.8 4993.7,1880.94 4993.7,1755.26 5004.77,1744.2 5027.92,1744.2 U10.41@5030.77,1741.34 ; U10.40@5035.39,1715.75 U10.41@5035.39,1741.34
NetC50_1: C50.1 R1.2 R2.2 U3.4 | length 1507.1
  Signal Layer 2 w12: v1(6135,2495) 6135,2424.63 6162.5,2397.13 6162.5,2355 6129,2321.5 6129,1247.5 6164,1212.5 v1(6165,1212.5)
  Bottom Layer w12: v1(6135,2495) 6135.56,2494.44 6135.56,2453.06 R2.2@6136.12,2452.5 R2.2@6140.06,2452.5 ; U3.4@6154.13,1127.4 6149.72,1127.4 6143.91,1133.21 6143.91,1157.21 6138.37,1162.75 6138.37,1166.69 6132.56,1172.5 C50.1@6128.62,1172.5 R1.2@6128.62,1212.5 v1(6165,1212.5)
NetC51_1: C51.1 C54.1 U1.3 U2.1 | length 139.5
  Bottom Layer w12: U2.1@5563.88,2346.69 U2.1@5569.69,2352.5
  Bottom Layer w15: U1.3@5450,2330 5451.81,2331.81 5490.69,2331.81 C54.1@5492.5,2333.62 C51.1@5532.5,2333.62 5532.5,2337.56 5536.81,2341.87 5548.68,2341.87 5559.31,2352.5 U2.1@5569.69,2352.5
NetC58_1: C58.1 D11.1 R11.2 U11.44 | length 286.9
  Top Layer w12: R11.2@5450.09,2009.19 R11.2@5450.39,2008.9 ; C58.1@5468.54,1869.55 C58.1@5477.5,1878.5
  Top Layer w15: D11.1@5397.5,2010 R11.2@5452.5,2011 5450.39,2008.9 5444.3,2002.8 5444.3,1912.69 5477.5,1879.49 C58.1@5477.5,1878.5 ; U11.44@5468.54,1800.39 C58.1@5468.54,1869.55
NetC59_1: C59.1 U11.51 U16.8 | length 649.7
  Top Layer w12.13: U11.51@5289.41,1800.39 U11.51@5290,1800.98
  Top Layer w15: U11.51@5289.41,1800.39 5288.05,1801.75 5288.05,1830.89 5261.81,1857.12 5261.81,1858.13 5245,1874.94 C59.1@5245,1878.88 5245,1882.82 5240.69,1887.13 5220.37,1887.13 5215,1892.5 5215,1904.99 5214.99,1985.01 5146.89,2053.11 5146.89,2160.61 5158.79,2172.5 5304.98,2172.5 5332.5,2144.98 U16.8@5332.5,2129.23
NetC60_1: C60.1 R12.2 U11.45 | length 132.2
  Top Layer w12: R12.2@5374.38,1878.88 C60.1@5417.5,1878.88 5417.5,1874.94 5442.95,1849.49 U11.45@5442.95,1800.39
NetC61_1: C61.1 R14.2 U11.50 | length 123.8
  Top Layer w12: R14.2@5288.12,1878.88 5309.69,1878.88 ; U11.50@5315,1800.39 5315,1873.57 5309.69,1878.88 ; C61.1@5331.25,1878.88 5309.69,1878.88
NetC62_2: C62.2 U11.40 U11.41 | length 200.7
  Top Layer w12: C62.2@5532.5,1881.3 5529.55,1881.3 5526.69,1878.44 5526.69,1875.49 5525,1873.8 5525,1758.58 5539.39,1744.2 5562.54,1744.2 U11.41@5565.39,1741.34
  Top Layer w12.13: U11.40@5565.39,1715.75 U11.41@5565.39,1741.34
NetC63_1: C63.1 R40.2 U9.2 | length 132.6
  Top Layer w15: C63.1@4190,2441.38 R40.2@4235,2441.38 ; U9.2@4192.5,2345.77 C63.1@4192.5,2433.33
NetC68_1: C68.1 R23.2 R24.2 U8.15 | length 144.3
  Top Layer w12: R24.2@5793.62,1547.5 R24.2@5794.51,1546.61 ; U8.15@5856.32,1546.61 U8.15@5857.2,1545.73
  Top Layer w15: C68.1@5793.62,1507.5 R24.2@5793.62,1547.5 R23.2@5793.62,1587.5 ; R24.2@5794.51,1546.61 U8.15@5856.32,1546.61
NetC69_1: C69.1 R26.1 U12.2 | length 105.2
  Top Layer w12: U12.2@6245,1213.23 6305.65,1213.23 6308.88,1210
  Top Layer w20: R26.1@6308.88,1190 6308.88,1210 C69.1@6308.88,1230
NetC70_1: C70.1 R29.1 U12.1 | length 127.1
  Top Layer w12: U12.1@6245,1187.64 6250.43,1187.64 6252.5,1185.57 6252.5,1172.5 6275,1150 C70.1@6308.88,1150 R29.1@6308.88,1110
NetC75_1: C75.1 R32.2 R33.2 U12.15 | length 144.9
  Top Layer w12: R33.2@5793.62,1222.5 5793.62,1210 R33.2@5796.85,1213.23
  Top Layer w15: C75.1@5793.62,1182.5 5793.62,1210 ; R33.2@5793.62,1222.5 R32.2@5793.62,1262.5 ; R33.2@5796.85,1213.23 U12.15@5857.2,1213.23
NetC86_1: C86.1 R60.2 U13.2 | length 126.3
  Top Layer w15: U13.2@4742.5,2345.77 C86.1@4742.5,2432.08 ; C86.1@4742.5,2441.38 R60.2@4782.5,2441.38
NetC98_1: C98.1 R74.2 U16.2 | length 145
  Top Layer w13.78: C98.1@5282.87,2441.9 C98.1@5283.13,2441.64 ; U16.2@5287.5,2345.77 5285.18,2348.08 5285.18,2439.58 C98.1@5283.13,2441.64 ; R74.2@5330,2441.38 5329.74,2441.64 C98.1@5283.13,2441.64
NetC100_1: C100.1 R3.2 R4.2 U3.3 | length 1435.3
  Signal Layer 2 w12: v1(6082.5,1127.5) 6110,1155 6110,2336.75 6135,2361.75 v1(6135,2365)
  Bottom Layer w12: R4.2@5945,1126.12 C100.1@5990,1126.12 5990.64,1126.76 6045.23,1126.76 U3.3@6045.87,1127.4 6045.92,1127.45 v1(6082.5,1127.5) v1(6082.5,1127.5) ; v1(6135,2365) 6135.56,2365.56 6135.56,2401.94 R3.2@6136.12,2402.5
NetD2_1: D2.1 R30.1 | length 80.9
  Bottom Layer w40: R30.1@3622.09,1010 3622.09,1015.66 3627.68,1021.25 3681.89,1021.25 3686.5,1025.86 D2.1@3686.5,1032.5
NetD2_2: D2.2 D3.1 | length 65.5
  Bottom Layer w50: D2.2@3873.5,1032.5 D3.1@3939,1032.5
NetD5_1: D5.1 R63.1 | length 46.1
  Bottom Layer w50: R63.1@5032.09,1012.5 D5.1@5068.01,1012.5 ; D5.1@5068.6,1000 5069,1000.39 D5.1@5069,1010
NetD5_2: D5.2 D6.1 | length 53
  Bottom Layer w50: D5.2@5276,1032.5 D6.1@5329,1032.5
NetL4_2: L4.2 U4.42 | length 263.8
  Top Layer w10: L4.2@3905,2003.13 3932.56,2003.13 3943.31,1992.38 L4.2@3943.31,1990.33 ; U4.42@3961.54,1779.72 U4.42@3962.5,1780.69
  Top Layer w15: L4.2@3943.31,1990.33 3962.5,1971.14 U4.42@3962.5,1780.69
NetL5_2: L5.2 U7.42 | length 281.1
  Top Layer w10: L5.2@4441.75,2003.43 L5.2@4487.26,2003.43 ; U7.42@4498.29,1780.02 U7.42@4507.5,1789.23
  Top Layer w15: L5.2@4487.26,2003.43 4507.5,1983.19 U7.42@4507.5,1789.23
NetL6_2: L6.2 U10.42 | length 257.1
  Top Layer w10: L6.2@5010,2000.63 5024.65,2000.63 L6.2@5035.39,1989.88 ; U10.42@5035.39,1779.72 U10.42@5047.5,1791.83
  Top Layer w15: U10.42@5025,1779.84 L6.2@5025,1990
NetL7_2: L7.2 U11.42 | length 255
  Top Layer w10: L7.2@5555,2003.13 5571.73,2003.13 5576.73,2003.13 L7.2@5582.56,2003.13
  Top Layer w12: U11.42@5565.39,1779.72 U11.42@5575.06,1789.39
  Top Layer w15: U11.42@5575.06,1789.39 L7.2@5575.06,2003.13
NetR2_1: R2.1 U2.6 | length 76.8
  Bottom Layer w19.68: U2.6@6012.07,2452.5 R2.1@6088.88,2452.5
NetR3_1: R3.1 U2.7 | length 76.8
  Bottom Layer w19.68: U2.7@6012.07,2402.5 R3.1@6088.88,2402.5
NetR6_1: R6.1 U9.6 | length 271.2
  Top Layer w12: U9.6@4142.5,2129.23 4142.5,2094.43 4306.88,1930.06 R6.1@4306.88,1926.12
NetR9_1: R9.1 U13.6 | length 264.9
  Top Layer w12: U13.6@4693.19,2128.54 U13.6@4692.5,2129.23 4692.5,2076.93 4839.38,1930.06 R9.1@4839.38,1926.12
NetR12_1: R12.1 U16.6 | length 261.9
  Top Layer w12: U16.6@5232.5,2129.23 5232.5,2071.93 5374.38,1930.06 R12.1@5374.38,1926.12
NetR17_2: R17.2 U5.16 | length 97.5
  Top Layer w12: R17.2@5793.62,1825 5799.43,1830.81 5805.38,1830.81 5831.02,1856.45 5831.02,1876.16 5833.09,1878.23 U5.16@5857.5,1878.23
NetR22_2: R22.2 U8.16 | length 96.8
  Top Layer w12: R22.2@5793.62,1467.5 5799.43,1473.31 5805.38,1473.31 5830.72,1498.66 5830.72,1518.07 5832.8,1520.14 U8.16@5857.2,1520.14
NetR27_1: R27.1 U6.6 | length 324.2
  Top Layer w12: U6.6@3542.5,2129.23 3542.5,2113.48 3673.96,1982.02 3719.21,1982.02 3754.85,1946.38 3754.85,1946.04 3770.83,1930.06 R27.1@3770.83,1926.12
NetR31_2: R31.2 U12.16 | length 89.3
  Top Layer w12: R31.2@5793.62,1142.5 5799.43,1148.31 5805.38,1148.31 5830.72,1173.66 5830.72,1185.57 5832.8,1187.64 U12.16@5857.2,1187.64
NetR42_1: R42.1 R46.2 | length 78.3
  Bottom Layer w12: R42.1@4517.09,2012.5 R46.2@4595.41,2012.5
NetR46_1: R46.1 R48.2 | length 78.1
  Bottom Layer w12: R46.1@4709.59,2012.5 4762.91,2012.5 R48.2@4780.41,2030
PGND: C1.2 C2.2 C3.2 C4.2 C20.2 C25.2 C26.2 C28.2 C52.1 C53.1 C55.1 C57.2 C63.2 C64.2 C65.2 C69.2 C70.2 C71.2 C72.2 C80.2 C86.2 C96.2 C98.2 C100.2 J2.2 J2.3 J2.11 J2.12 NT1.1 R4.1 U2.5 U3.2 U5.5 U5.6 U5.7 U5.8 U6.4 U8.5 U8.6 U8.7 U8.8 U9.4 U12.5 U12.6 U12.7 U12.8 U13.4 U16.4 | length 965.7
  Top Layer w25: U6.4@3492.5,2345.77 v1(3492.5,2395) ; v1(3565,2480) 3591.81,2480 3592.5,2480.69 C26.2@3592.5,2481.12 ; C20.2@3710,2409 3711.5,2407.5 v1(3752.5,2407.5) ; U9.4@4092.5,2345.77 v1(4092.5,2397.5) ; v1(4162.5,2487.5) 4189.31,2487.5 4190,2488.19 C63.2@4190,2488.62 ; C57.2@4310,2409 4311.5,2407.5 v1(4352.5,2407.5) ; U13.4@4642.5,2345.77 v1(4642.5,2395) ; v1(4707.5,2487.5) 4741.81,2487.5 4742.5,2488.19 C86.2@4742.5,2488.62 ; v1(4817.5,2407.5) 4849,2407.5 C80.2@4850,2406.5 ; v1(5152.5,2352.5) 5181.81,2352.5 5182.5,2351.81 U16.4@5182.5,2345.77 ; v1(5282.5,2525) 5282.5,2489.51 C98.2@5282.87,2489.14 ; C96.2@5385,2404 5385,2403.01 5407.82,2380.19 5417.31,2380.19 v1(5427.5,2370) ; C70.2@6356.12,1150 v1(6390,1150) ; C69.2@6356.12,1230 v1(6390,1230) ; C28.2@6356.12,1480 v1(6390,1480) ; C25.2@6356.12,1560 v1(6390,1560) ; C2.2@6356.12,1832.5 v1(6387.5,1832.5) ; C1.2@6356.12,1912.5 v1(6387.5,1912.5)
  Bottom Layer w25: v1(5945,1047.5) R4.1@5945,1078.88 C100.2@5990,1078.88 5990,1081.44 5997.87,1089.31 6045.18,1089.31 U3.2@6045.87,1090 ; U2.5@6012.07,2502.5 6014.31,2502.5 6015,2503.19 v1(6015,2530) ; C55.1@6058.62,2262.5 C52.1@6058.62,2305 6059.31,2304.31 v1(6085,2305) ; C53.1@6212.5,1103.62 v1(6212.5,1142.5)
  other v1: 5700,995 5725,995 5700,1020 5725,1020 5727.5,1052.5 5752.5,1052.5 5777.5,1052.5 5802.5,1052.5 5727.5,1077.5 5752.5,1077.5 5777.5,1077.5 5802.5,1077.5 6385,1342.5 6305,1345 6304.17,1372.5 6339.17,1372.5 6375,1372.5 6242.5,1400 6272.5,1400 6305,1400 6340,1400 6375,1400 6298.33,1697.5 6339.17,1697.5 6380,1697.5 6258.33,1725 6299.17,1725 6340,1725 6380.83,1725 6258.33,1755 6299.17,1755 6340,1755 6380.83,1755 6300.83,2035 6300.83,2065 6342.5,2065 6382.5,2065 6260,2095 6300.83,2095 6341.67,2095 6382.5,2095 6260,2125 6300.83,2125 6341.67,2125 6382.5,2125
SGND_H2A: C11.2 C12.1 C13.1 C14.1 C15.1 C16.1 C17.1 C18.1 C19.1 C21.2 C22.2 C23.2 C24.2 C27.2 C29.1 C31.2 D3.2 D8.2 L4.1 R7.1 R17.1 R19.1 R42.2 U4.18 U4.19 U4.20 U4.21 U4.22 U4.23 U4.24 U4.25 U4.26 U4.28 U4.29 U4.30 U4.31 U4.32 U4.33 U4.34 U4.35 U4.36 U4.37 U4.38 U4.39 U5.9 U5.10 U5.11 U5.14 U6.5 U7.2 U7.3 U7.4 U7.5 U7.6 U7.7 U7.8 U7.9 U7.10 U7.11 U7.12 U7.13 U7.14 U7.15 | length 7009.3
  Top Layer w12: U5.14@5857.5,1929.41 5857.8,1929.7 5904.7,1929.7 v1(5905,1930)
  Top Layer w13.78: U4.18@3685.55,1349.61 3685.55,1393.05 3687.5,1395 ; U4.19@3711.14,1349.61 3711.14,1396.14 3712.5,1397.5 ; U4.20@3736.73,1349.61 3736.73,1396.73 3737.5,1397.5 ; 3760,1397.5 3762.32,1395.18 U4.21@3762.32,1349.61 ; 3787.5,1397.5 3787.91,1397.09 U4.22@3787.91,1349.61 ; U4.23@3813.5,1349.61 3813.5,1396 3815,1397.5 ; 3837.5,1397.5 3839.09,1395.91 U4.24@3839.09,1349.61 ; U4.25@3864.69,1349.61 3864.69,1397.18 3865,1397.5 ; 3890,1400 3890.28,1399.72 U4.26@3890.28,1349.61 ; 3910,1435 3910.75,1434.25 U4.29@3961.54,1434.25 U7.14@4045.37,1434.25 4046.12,1435 4077.5,1435 ; 3912.5,1407.5 3913.66,1408.66 U4.28@3961.54,1408.66 U7.15@4045.37,1408.66 4046.71,1410 4075,1410 ; 3912.5,1460 3912.66,1459.84 U4.30@3961.54,1459.84 U7.13@4045.37,1459.84 4045.52,1460 4077.5,1460 ; 3912.5,1485 3912.93,1485.43 U4.31@3961.54,1485.43 U7.12@4045.37,1485.43 4045.8,1485 4080,1485 ; v1@3912.5,1640 3913.52,1638.98 U4.37@3961.54,1638.98 U7.6@4045.37,1638.98 4046.84,1637.5 4080,1637.5 ; v1@3912.5,1665 3912.93,1664.57 U4.38@3961.54,1664.57 U7.5@4045.37,1664.57 4045.8,1665 4080,1665 ; 3912.5,1690 3912.66,1690.16 U4.39@3961.54,1690.16 U7.4@4045.37,1690.16 4045.52,1690 4080,1690 ; 3915,1510 3916.02,1511.02 U4.32@3961.54,1511.02 U7.11@4045.37,1511.02 4046.84,1512.5 4077.5,1512.5 ; v1@3915,1612.5 3915.89,1613.39 U4.36@3961.54,1613.39 U7.7@4045.37,1613.39 4046.25,1612.5 4080,1612.5 ; v1@3917.5,1535 3919.11,1536.61 U4.33@3961.54,1536.61 U7.10@4045.37,1536.61 4046.25,1537.5 4080,1537.5 ; v1@3917.5,1562.5 3917.8,1562.2 U4.34@3961.54,1562.2 U7.9@4045.37,1562.2 4045.66,1562.5 4080,1562.5 ; v1@3917.5,1587.5 3917.8,1587.8 U4.35@3961.54,1587.8 U7.8@4045.37,1587.8 4045.66,1587.5 4077.5,1587.5 ; U7.3@4045.37,1715.75 4046.12,1715 4080,1715 ; U7.2@4045.37,1741.34 4046.71,1740 4080,1740 ; U7.14@4047.35,1434.4 U7.14@4047.5,1434.55 ; U7.12@4047.35,1485.58 U7.12@4047.5,1485.73 ; U7.11@4047.35,1511.17 U7.11@4047.5,1511.32
  Top Layer w15: U5.9@5857.5,2057.36 v1(5857.5,2075)
  Top Layer w20: C31.2@3812.5,1926.12 v1(3812.5,1957.5) ; C11.2@3877.5,1946.5 3883.23,1940.77 3911.73,1940.77 v1(3912.5,1940) 3913.27,1939.23 3913.27,1932.27 3931.83,1913.7 C29.1@3932.5,1913.7 3933.09,1913.7 C29.1@3934.23,1914.84 ; C22.2@5745,2055.51 C22.2@5745,2056.5 ; C22.2@5747.5,2056.5 5747.5,2055.51 5756.2,2046.81 5757.19,2046.81 5762.13,2041.87 5795.69,2041.87 C23.2@5795.69,2034
  Top Layer w25: v1(3492.5,2082.5) U6.5@3492.5,2129.23 ; C21.2@3645,1926.12 3645,1925.69 3645.69,1925 v1(3667.5,1925) 3686.81,1925 R7.1@3687.5,1925.69 ; R7.1@3687.5,1926.12 R7.1@3687.5,1925.69 ; C27.2@3729.17,1926.12 3729.17,1925.69 3728.48,1925 3688.19,1925 R7.1@3687.5,1925.69 ; v1(3742.5,2097.14) D8.2@3742.5,2139.47 ; v1(3855,2035) 3855,2059.43 3877.44,2081.87 L4.1@3905,2081.87 ; R17.1@5746.38,1825 R19.1@5746.38,1905
  Signal Layer 2 w25: v1(5747.5,1885) 5857.5,1995 v1(5857.5,2075)
  Signal Layer 3 w25: v1(3742.5,2097.14) 3742.5,2140 3880,2277.5 5205,2277.5 5227.5,2300 5227.5,2302.5 5560,2302.5 5817.5,2045 5817.5,2030
  Bottom Layer w12: 4402.5,1875 4402.91,1875.41 R42.2@4402.91,2012.5
  Bottom Layer w50: D3.2@4126,1032.5 4206.99,1032.5 4221.36,1046.87 C12.1@4221.36,1067.5 ; C17.1@4612.61,1776.25 C17.1@4613.86,1777.5
  Bottom Layer w70: C15.1@4230,1772.7 4332.3,1875 4402.5,1875 4575.41,1875 4613.86,1836.56 C17.1@4613.86,1777.5 ; C16.1@4612.61,1138.75 C17.1@4612.61,1776.25
  other v1: 3880,1535 3907.5,1535 4127.5,1535 4106,1547.5 4149,1547.5 3880,1560.5 3907.5,1560.5 4127.5,1560 4106,1572.5 4149,1572.5 4127.5,1585 3880,1586 3907.5,1586 4106,1597.5 4149,1597.5 4127.5,1610 3880,1611.5 3907.5,1611.5 4106,1622.5 4149,1622.5 4127.5,1635 3880,1637 3907.5,1637 4104,1647.5 4149,1647.5 4126.5,1660 3880,1662.5 3907.5,1662.5 4105,1672.5 4148,1672.5 4126.5,1685 3707.5,1925 5907.5,2007.5 5907.5,2035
